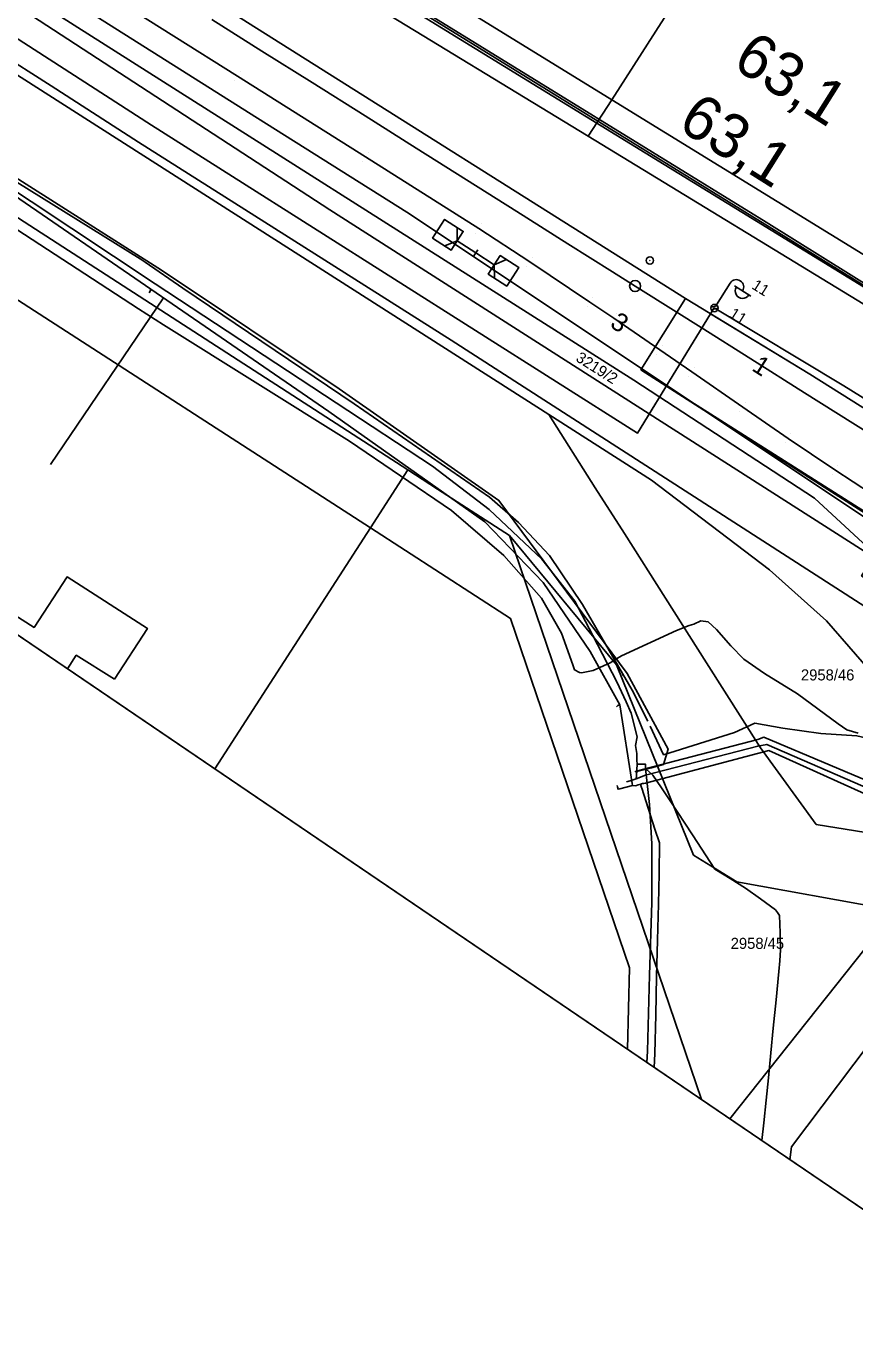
# Model space of a CAD drawing. Extents: x -621145 to -620110, y -1122807 to -1121971.
# Drawn here: x -620628.4 to -620515.9, y -1122662.4 to -1122484.3 of the extents above; entities that cross this region are included whole.
import ezdxf

# ---------------------------------------------------------------- set-up
doc = ezdxf.new("R2010")
doc.units = 0
for name, color, linetype in [('060601_EOV', 7, 'Continuous'), ('060604_ROZVODY_SEE', 7, 'Continuous'), ('CETIN', 7, 'Continuous'), ('GasNet', 7, 'Continuous'), ('itself', 7, 'Continuous'), ('PS 06-14-01_trasa_sdělovací_nové', 7, 'Continuous'), ('RÁMY', 7, 'Continuous'), ('SEE', 7, 'Continuous'), ('SSZT', 7, 'Continuous'), ('SSZT-DK', 7, 'Continuous'), ('UZEMNĚNÍ', 7, 'Continuous'), ('VAS stoka', 7, 'Continuous'), ('VAS vodovod', 7, 'Continuous'), ('Vrstva 1', 7, 'Continuous'), ('Vrstva 25', 7, 'Continuous'), ('Vrstva 53', 7, 'Continuous'), ('Vrstva 55', 7, 'Continuous'), ('Vrstva 56', 7, 'Continuous'), ('Vrstva 57', 7, 'Continuous'), ('Vrstva 62', 7, 'Continuous'), ('Vrstva 7', 7, 'Continuous'), ('ČD-T', 7, 'Continuous')]:
    doc.layers.add(name, color=color, linetype=linetype)

msp = doc.modelspace()

# ---------------------------------------------------------------- linework, layer by layer
at = {"layer": '060601_EOV'}
msp.add_lwpolyline([(-620343.18, -1122658.46), (-620368.5, -1122642.9), (-620411.56, -1122614.92), (-620424.16, -1122607.09), (-620443.53, -1122595), (-620456.11, -1122587.12), (-620447.82, -1122572.96), (-620450.95, -1122571.45), (-620470.59, -1122561.48), (-620499.61, -1122545.57), (-620522.04, -1122531.47), (-620538.89, -1122521.21), (-620599.21, -1122483.22), (-620683.52, -1122429.44)], dxfattribs=at)
at = {"layer": '060604_ROZVODY_SEE'}
msp.add_line((-620535, -1122522.48), (-620535.49, -1122523.28), dxfattribs=at)
msp.add_lwpolyline([(-620443.53, -1122595), (-620456.11, -1122587.12), (-620447.82, -1122572.96), (-620450.95, -1122571.45), (-620470.59, -1122561.48), (-620499.61, -1122545.57), (-620522.04, -1122531.47), (-620538.89, -1122521.21), (-620599.21, -1122483.22), (-620683.52, -1122429.44), (-620756.33, -1122383.52), (-620765.8, -1122398.39)], dxfattribs=at)
at = {"layer": 'CETIN'}
for points in [[(-620926.41, -1122268.7), (-620748.44, -1122376.27), (-620484.52, -1122538.15)], [(-620646.43, -1122495.05), (-620612.92, -1122515.84), (-620612.23, -1122516.26), (-620607.1, -1122519.79), (-620583.87, -1122535.51), (-620565.48, -1122548.17), (-620561.56, -1122551.58), (-620557.36, -1122556.05), (-620552.9, -1122562.72), (-620546.13, -1122574.35), (-620544.03, -1122578.53)], [(-620607.1, -1122519.79), (-620612.23, -1122516.26)], [(-620547.37, -1122572.22), (-620547.52, -1122572.29)], [(-620543.69, -1122579.2), (-620541.87, -1122583.1), (-620532.27, -1122580.05), (-620529.5, -1122578.82), (-620525.69, -1122579.49), (-620520.52, -1122580.2), (-620515.66, -1122580.54), (-620511.76, -1122581.44), (-620509.68, -1122582.26), (-620506.2, -1122582.41), (-620494.32, -1122581.82), (-620491.48, -1122581.44), (-620483.44, -1122578.57)], [(-620532.27, -1122580.05), (-620541.87, -1122583.1)]]:
    msp.add_lwpolyline(points, dxfattribs=at)
at = {"layer": 'GasNet'}
for points in [[(-620639.06, -1122500.54), (-620610.88, -1122519.2), (-620586.31, -1122535.34), (-620573.22, -1122543.96), (-620565.55, -1122549.81), (-620558.39, -1122556.56), (-620553.9, -1122562.25), (-620551.49, -1122566.93), (-620548.21, -1122573.19), (-620546.94, -1122575.89), (-620546.29, -1122577.44), (-620545.44, -1122580.66), (-620545.67, -1122581.84), (-620545.49, -1122582.92), (-620545.5, -1122583.84), (-620545.45, -1122584.35), (-620545.55, -1122585.95), (-620545.62, -1122586.36)], [(-620545.62, -1122586.36), (-620544.33, -1122585.86), (-620529.1, -1122581.91), (-620527.88, -1122581.68), (-620501.79, -1122593.01), (-620500.52, -1122592.53), (-620484.13, -1122585.56), (-620478.57, -1122583.14), (-620474.2, -1122586.82), (-620449.91, -1122606.86), (-620450.02, -1122607.5), (-620458.5, -1122620.02), (-620458.8, -1122620.62), (-620432.06, -1122640.49), (-620425.64, -1122643.91), (-620417.98, -1122647.99), (-620389.11, -1122672.47), (-620361.34, -1122696.38), (-620351.16, -1122708.72), (-620351, -1122709.02), (-620350.83, -1122709.39), (-620350.53, -1122710.79), (-620349.5, -1122710.44), (-620336.68, -1122702.48)], [(-620545.45, -1122584.35), (-620544.34, -1122584.36), (-620544.31, -1122584.94), (-620543.79, -1122589.85), (-620543.45, -1122595.16)], [(-620545.62, -1122586.36), (-620546.42, -1122586.61), (-620546.89, -1122586.78)], [(-620543.45, -1122595.16), (-620543.47, -1122603.15), (-620543.79, -1122613), (-620544.07, -1122623.3), (-620544.13, -1122624.83)]]:
    msp.add_lwpolyline(points, dxfattribs=at)
at = {"layer": 'itself'}
msp.add_lwpolyline([(-620515.49, -1122580.17), (-620517.02, -1122579.72), (-620518.2, -1122578.89), (-620523.69, -1122574.82), (-620528.2, -1122572.08), (-620530.97, -1122570.13), (-620532.77, -1122568.3), (-620534.7, -1122566.11), (-620535.82, -1122565.08), (-620536.83, -1122564.91), (-620537.77, -1122565.36), (-620538.42, -1122565.55), (-620540.13, -1122566.23), (-620547.57, -1122569.68), (-620548.37, -1122570.13), (-620549.14, -1122570.64), (-620551.44, -1122571.66), (-620553.02, -1122571.98), (-620553.03, -1122571.98), (-620553.3, -1122571.94), (-620553.95, -1122571.56), (-620554.18, -1122570.9), (-620555.72, -1122566.58), (-620558.44, -1122561.86), (-620563.55, -1122556.05), (-620570.67, -1122549.95), (-620584.48, -1122540.56), (-620609.76, -1122524.78), (-620613.13, -1122522.62), (-620616.25, -1122520.59), (-620644.13, -1122502.42)], dxfattribs=at)
at = {"layer": 'PS 06-14-01_trasa_sdělovací_nové'}
for points in [[(-620538.89, -1122521.21), (-620538.89, -1122521.21), (-620599.21, -1122483.22), (-620683.52, -1122429.44), (-620756.33, -1122383.52), (-620761.98, -1122392.4), (-620753.37, -1122398.54), (-620735.26, -1122410.11), (-620735.26, -1122410.11)], [(-620248.32, -1122722.77), (-620259.89, -1122713.57), (-620277.71, -1122700.89), (-620282.35, -1122705.3), (-620297.82, -1122689.49), (-620310.82, -1122680.06), (-620322.23, -1122672.32), (-620343.18, -1122658.46), (-620368.5, -1122642.9), (-620411.56, -1122614.92), (-620456.11, -1122587.12), (-620544.95, -1122530.86), (-620538.89, -1122521.21), (-620538.89, -1122521.21), (-620538.89, -1122521.21)]]:
    msp.add_lwpolyline(points, dxfattribs=at)
at = {"layer": 'RÁMY'}
for points in [[(-621061.56, -1122093.92), (-620192.94, -1122683.83), (-620276.37, -1122806.68), (-621144.99, -1122216.77)], [(-620887.83, -1122211.9), (-620192.94, -1122683.83), (-620276.37, -1122806.68), (-620971.26, -1122334.75)]]:
    msp.add_lwpolyline(points, close=True, dxfattribs=at)
at = {"layer": 'SEE'}
msp.add_lwpolyline([(-620244.52, -1122694.3), (-620246.55, -1122692.66), (-620267.47, -1122718.6), (-620268.22, -1122719.53), (-620284.41, -1122704.62), (-620304.33, -1122686.26), (-620309.55, -1122681.45), (-620327.71, -1122669.48), (-620362.83, -1122646.34), (-620390.25, -1122629.02), (-620411.93, -1122614.96), (-620423.13, -1122608.01), (-620468.34, -1122579.91), (-620468.34, -1122579.91), (-620460.94, -1122568.1), (-620517.42, -1122533.03), (-620535, -1122522.48), (-620545.41, -1122539.45), (-620611.37, -1122497.7), (-620665.57, -1122462.75)], dxfattribs=at)
at = {"layer": 'SSZT'}
msp.add_lwpolyline([(-620879.24, -1122313.32), (-620842.99, -1122336.61), (-620835.05, -1122343.25), (-620812.66, -1122358.95), (-620764.9, -1122389.75), (-620688.59, -1122438.97), (-620596.98, -1122496.73), (-620576.74, -1122509.48), (-620506.75, -1122556.12), (-620447.29, -1122593.62), (-620363.27, -1122647.56), (-620313.97, -1122679.22), (-620306.51, -1122669.29), (-620273.14, -1122696.27), (-620258.42, -1122709.14), (-620248.07, -1122696.09)], dxfattribs=at)
at = {"layer": 'SSZT-DK'}
msp.add_lwpolyline([(-620927.29, -1122269.99), (-620900.27, -1122286.47), (-620889.15, -1122293.45), (-620783.74, -1122358.82), (-620712.75, -1122398.18), (-620653.12, -1122435.23), (-620617.36, -1122456.74), (-620574.42, -1122482.6), (-620528.16, -1122511.11), (-620496.31, -1122530.83), (-620515.02, -1122558.81), (-620500.38, -1122568.61), (-620465.39, -1122591.45), (-620452.16, -1122605.02), (-620438.23, -1122615.5), (-620392.31, -1122655.21), (-620359.04, -1122685.8), (-620308.77, -1122717.8), (-620291.41, -1122732.21), (-620277.2, -1122744.11), (-620257.61, -1122720.05), (-620250.25, -1122710.72), (-620233.29, -1122724.26), (-620225.35, -1122731.56)], dxfattribs=at)
at = {"layer": 'UZEMNĚNÍ'}
msp.add_lwpolyline([(-620535, -1122522.48), (-620535.49, -1122523.28), (-620522.04, -1122531.47), (-620499.61, -1122545.57), (-620487.51, -1122552.2), (-620470.59, -1122561.48), (-620459.3, -1122567.21), (-620458.67, -1122565.97)], dxfattribs=at)
at = {"layer": 'VAS stoka'}
for points in [[(-620781.72, -1122408.87), (-620776.69, -1122412.14), (-620774.2, -1122412.02), (-620772.21, -1122412.95), (-620766.77, -1122415.95), (-620758.11, -1122421.89), (-620737.16, -1122435.39), (-620726.71, -1122442.22), (-620705.9, -1122455.54), (-620681.71, -1122471.08), (-620665.23, -1122481.83), (-620655.61, -1122488.12), (-620638.12, -1122499.53), (-620609.99, -1122517.38), (-620585.88, -1122533.44), (-620564.23, -1122548.6), (-620546.83, -1122572.05), (-620541.25, -1122582.33), (-620541.87, -1122584.42), (-620543.53, -1122584.85), (-620544.25, -1122585.03)], [(-620544.25, -1122585.03), (-620545.68, -1122585.41), (-620545.7, -1122585.34), (-620544.74, -1122585.09), (-620529.09, -1122581.01), (-620528.27, -1122580.72), (-620501.26, -1122592.08), (-620484.32, -1122584.76), (-620478.68, -1122582.19), (-620475.52, -1122584.33), (-620473.62, -1122582.33), (-620454.46, -1122552.49), (-620449.28, -1122555.81), (-620438.79, -1122557.25), (-620438.13, -1122557.28)], [(-620528.56, -1122635.4), (-620528.28, -1122633.03), (-620527.95, -1122629.96), (-620527.63, -1122626.89), (-620527.31, -1122623.54), (-620526.99, -1122620.19), (-620526.62, -1122616.34), (-620526.25, -1122612.49), (-620526.12, -1122611.03), (-620525.99, -1122609.57), (-620526.07, -1122607.23), (-620526.16, -1122604.89), (-620526.43, -1122604.5), (-620526.7, -1122604.12), (-620528.73, -1122602.65), (-620530.75, -1122601.19), (-620532.84, -1122599.89), (-620534.92, -1122598.59), (-620537.95, -1122593.97), (-620540.97, -1122589.34), (-620542.16, -1122587.59), (-620543.34, -1122585.84), (-620543.8, -1122585.43), (-620544.25, -1122585.03)]]:
    msp.add_lwpolyline(points, dxfattribs=at)
at = {"layer": 'VAS vodovod'}
msp.add_line((-620609.72, -1122521.13), (-620625.07, -1122543.73), dxfattribs=at)
for points in [[(-620783.05, -1122410.36), (-620779.49, -1122412.44), (-620776.82, -1122413.57), (-620766.15, -1122419), (-620759.23, -1122423.16), (-620738.05, -1122436.88), (-620666.7, -1122483.31), (-620630.69, -1122506.76), (-620611.44, -1122519.95), (-620587.32, -1122536.52), (-620566.14, -1122551.51), (-620558.22, -1122559.71), (-620551.85, -1122569.08), (-620547.83, -1122576.32), (-620546.15, -1122586.98), (-620546.1, -1122587.26)], [(-620611.68, -1122520.43), (-620611.56, -1122520.19), (-620611.44, -1122519.95)], [(-620548.28, -1122576.61), (-620548.08, -1122576.43), (-620547.83, -1122576.32)], [(-620544.97, -1122587.1), (-620544.86, -1122587.05), (-620544.76, -1122587), (-620544.54, -1122586.97), (-620544.31, -1122586.94), (-620527.61, -1122582.53), (-620502.02, -1122594.03), (-620500.78, -1122593.46), (-620500.1, -1122593.23), (-620483.67, -1122586.38), (-620481.33, -1122585.41), (-620479.58, -1122584.86), (-620478.41, -1122584.64), (-620477.75, -1122585.1), (-620476.87, -1122585.61)], [(-620546.1, -1122587.26), (-620547.82, -1122587.71), (-620548.06, -1122587.76), (-620548.14, -1122587.45), (-620548.19, -1122587.25)], [(-620546.1, -1122587.26), (-620545.74, -1122587.29), (-620545.54, -1122587.24), (-620545.34, -1122587.19), (-620545.15, -1122587.14), (-620544.97, -1122587.1)], [(-620544.97, -1122587.1), (-620544.95, -1122587.25), (-620544.93, -1122587.4), (-620544.87, -1122587.52), (-620544.81, -1122587.64), (-620544.23, -1122589.49), (-620543.66, -1122591.34), (-620543.05, -1122593.19), (-620542.44, -1122595.03), (-620542.49, -1122599.19), (-620542.55, -1122603.34), (-620542.69, -1122608.25), (-620542.83, -1122613.15), (-620542.95, -1122618.38), (-620543.07, -1122623.6), (-620543.15, -1122625.5)]]:
    msp.add_lwpolyline(points, dxfattribs=at)
at = {"layer": 'Vrstva 1'}
msp.add_line((-620544.95, -1122530.86), (-620538.89, -1122521.21), dxfattribs=at)
for points in [[(-620538.89, -1122521.21), (-620599.21, -1122483.22), (-620683.52, -1122429.44), (-620747.38, -1122389.13), (-620756.33, -1122383.52)], [(-620616.99, -1122480.17), (-620599.71, -1122491.04), (-620582.33, -1122501.97), (-620566.97, -1122511.73), (-620560.03, -1122516.24), (-620551.87, -1122521.69), (-620548.62, -1122523.89), (-620542.4, -1122528.15), (-620538.06, -1122531.16), (-620531.12, -1122535.95), (-620524.97, -1122540.18), (-620518.62, -1122544.43), (-620513.65, -1122547.7)], [(-620603.19, -1122483.36), (-620596.39, -1122487.64), (-620589.57, -1122491.93), (-620582.39, -1122496.45), (-620575.44, -1122500.82), (-620568.6, -1122505.12), (-620561.8, -1122509.42), (-620554.88, -1122513.77), (-620548.82, -1122517.58), (-620545.74, -1122519.52), (-620540.16, -1122523.03), (-620536.76, -1122525.16), (-620530.04, -1122529.4), (-620522.74, -1122534), (-620516.18, -1122538.13), (-620510.88, -1122541.46)], [(-620603.19, -1122483.36), (-620596.39, -1122487.64), (-620589.57, -1122491.93), (-620582.39, -1122496.45), (-620575.44, -1122500.82), (-620568.6, -1122505.12), (-620561.8, -1122509.42), (-620554.88, -1122513.77), (-620548.82, -1122517.58), (-620545.74, -1122519.52), (-620540.16, -1122523.03), (-620536.76, -1122525.16), (-620530.04, -1122529.4), (-620522.74, -1122534), (-620516.18, -1122538.13), (-620510.88, -1122541.46)], [(-620456.11, -1122587.12), (-620500.01, -1122559.59), (-620522.22, -1122545.45), (-620544.95, -1122530.86)]]:
    msp.add_lwpolyline(points, dxfattribs=at)
at = {"layer": 'Vrstva 25'}
for p, q in [((-620534.71, -1122522.08), (-620532.84, -1122519.12)), ((-620534.71, -1122522.08), (-620532.84, -1122519.12)), ((-620532.25, -1122519.49), (-620530.05, -1122520.88)), ((-620532.25, -1122519.49), (-620530.05, -1122520.88)), ((-620535.46, -1122522.37), (-620534.6, -1122522.18)), ((-620535.46, -1122522.37), (-620534.6, -1122522.18)), ((-620535.41, -1122522.74), (-620534.48, -1122522.53)), ((-620535.41, -1122522.74), (-620534.48, -1122522.53))]:
    msp.add_line(p, q, dxfattribs=at)
msp.add_circle((-620534.98, -1122522.5), 0.5, dxfattribs=at)
msp.add_circle((-620534.98, -1122522.5), 0.5, dxfattribs=at)
for centre, start, end in [((-620532, -1122519.65), 327.7645, 147.7645), ((-620532, -1122519.65), 327.7645, 147.7645), ((-620531.16, -1122520.19), 147.0619, 328.467), ((-620531.16, -1122520.19), 147.0619, 328.467)]:
    msp.add_arc(centre, 1, start, end, dxfattribs=at)
at = {"layer": 'Vrstva 53'}
for p, q in [((-620545.92, -1122532.26), (-620679.51, -1122447.56)), ((-620638.48, -1122446.57), (-620552.09, -1122499.2)), ((-620552.09, -1122499.2), (-620445.8, -1122563.95)), ((-620521.41, -1122548.27), (-620545.92, -1122532.26)), ((-620511.29, -1122557.64), (-620521.41, -1122548.27))]:
    msp.add_line(p, q, dxfattribs=at)
at = {"layer": 'Vrstva 55'}
for p, q in [((-620688.16, -1122408.5), (-620548.9, -1122494.24)), ((-620545.92, -1122532.26), (-620679.51, -1122447.56)), ((-620638.48, -1122446.57), (-620552.09, -1122499.2)), ((-620557.45, -1122536.96), (-620684.91, -1122455.63)), ((-620548.9, -1122494.24), (-620525.58, -1122457.92)), ((-620587.17, -1122509.18), (-620645.72, -1122471.03)), ((-620576.58, -1122544.45), (-620660.74, -1122490.09)), ((-620552.09, -1122499.2), (-620548.9, -1122494.24)), ((-620548.9, -1122494.24), (-620475.79, -1122539.24)), ((-620552.09, -1122499.2), (-620445.8, -1122563.95)), ((-620657.43, -1122503.38), (-620581.67, -1122552.32)), ((-620511.29, -1122557.64), (-620587.17, -1122509.18)), ((-620521.41, -1122548.27), (-620545.92, -1122532.26)), ((-620557.45, -1122536.96), (-620551.15, -1122546.87)), ((-620543.5, -1122545.86), (-620557.45, -1122536.96)), ((-620581.67, -1122552.32), (-620576.58, -1122544.45)), ((-620543.5, -1122545.86), (-620527.5, -1122558.02)), ((-620551.15, -1122546.87), (-620547.19, -1122553.1)), ((-620511.29, -1122557.64), (-620521.41, -1122548.27)), ((-620581.67, -1122552.32), (-620602.78, -1122585)), ((-620548.28, -1122570.88), (-620562.8, -1122553.35)), ((-620562.8, -1122553.35), (-620536.71, -1122629.87)), ((-620547.19, -1122553.1), (-620536.04, -1122570.64)), ((-620519.77, -1122564.93), (-620527.5, -1122558.02)), ((-620511.02, -1122574.99), (-620519.77, -1122564.93)), ((-620537.83, -1122596.73), (-620548.28, -1122570.88)), ((-620536.04, -1122570.64), (-620528.72, -1122582.15)), ((-620528.72, -1122582.15), (-620521.17, -1122592.53)), ((-620521.17, -1122592.53), (-620510.22, -1122594.3)), ((-620531.96, -1122600.32), (-620537.83, -1122596.73)), ((-620510.44, -1122604.21), (-620531.96, -1122600.32)), ((-620532.9, -1122632.46), (-620510.44, -1122604.21)), ((-620503.19, -1122607.95), (-620524.52, -1122636.25)), ((-620524.73, -1122638.01), (-620524.52, -1122636.25))]:
    msp.add_line(p, q, dxfattribs=at)
for points in [[(-620562.8, -1122553.35), (-620572.54, -1122547.06), (-620576.58, -1122544.45)], [(-620659.82, -1122546.26), (-620659.27, -1122545.41), (-620652.1, -1122549.99), (-620627.31, -1122565.82), (-620622.82, -1122558.97), (-620611.91, -1122565.95), (-620616.39, -1122572.84)], [(-620581.67, -1122552.32), (-620562.67, -1122564.59), (-620546.5, -1122612), (-620546.78, -1122623.03)], [(-620616.39, -1122572.84), (-620621.58, -1122569.6), (-620622.76, -1122571.43)]]:
    msp.add_lwpolyline(points, dxfattribs=at)
at = {"layer": 'Vrstva 56'}
for p, q in [((-620648.08, -1122477.56), (-620625, -1122492.37)), ((-620625, -1122492.37), (-620613.12, -1122500)), ((-620570.69, -1122526.84), (-620613.12, -1122500)), ((-620504.94, -1122569.2), (-620570.69, -1122526.84))]:
    msp.add_line(p, q, dxfattribs=at)
at = {"layer": 'Vrstva 62'}
for p, q in [((-620599.33, -1122490.43), (-620599.33, -1122490.43)), ((-620600.08, -1122491.66), (-620600.08, -1122491.66)), ((-620581.93, -1122501.35), (-620581.93, -1122501.35)), ((-620582.73, -1122502.59), (-620582.73, -1122502.59)), ((-620567.35, -1122512.35), (-620567.35, -1122512.35)), ((-620566.6, -1122511.1), (-620566.6, -1122511.1)), ((-620559.63, -1122515.64), (-620559.63, -1122515.64)), ((-620560.43, -1122516.84), (-620560.43, -1122516.84)), ((-620551.48, -1122521.07), (-620551.48, -1122521.07)), ((-620552.26, -1122522.3), (-620552.26, -1122522.3)), ((-620549.02, -1122524.5), (-620549.02, -1122524.5)), ((-620548.22, -1122523.28), (-620548.22, -1122523.28)), ((-620542.01, -1122527.53), (-620542.01, -1122527.53)), ((-620542.78, -1122528.77), (-620542.78, -1122528.77)), ((-620538.47, -1122531.76), (-620538.47, -1122531.76)), ((-620537.66, -1122530.55), (-620537.66, -1122530.55)), ((-620530.74, -1122535.33), (-620530.74, -1122535.33)), ((-620531.51, -1122536.57), (-620531.51, -1122536.57)), ((-620525.34, -1122540.79), (-620525.34, -1122540.79)), ((-620524.59, -1122539.57), (-620524.59, -1122539.57)), ((-620518.23, -1122543.81), (-620518.23, -1122543.81)), ((-620519, -1122545.04), (-620519, -1122545.04))]:
    msp.add_line(p, q, dxfattribs=at)
at = {"layer": 'Vrstva 7'}
for p, q in [((-620569.89, -1122513.37), (-620567.37, -1122515.01)), ((-620567.64, -1122515.43), (-620567.1, -1122514.59)), ((-620567.1, -1122514.59), (-620567.64, -1122515.43)), ((-620564.86, -1122516.64), (-620567.37, -1122515.01)), ((-620543.78, -1122516.02), (-620543.69, -1122516.08)), ((-620543.78, -1122516.02), (-620543.69, -1122516.08))]:
    msp.add_line(p, q, dxfattribs=at)
for points in [[(-620569.89, -1122513.37), (-620569.07, -1122512.11), (-620571.59, -1122510.48), (-620573.22, -1122513), (-620570.7, -1122514.63), (-620569.89, -1122513.37)], [(-620571.55, -1122514.08), (-620569.89, -1122513.37), (-620569.91, -1122511.57)], [(-620564.86, -1122516.64), (-620565.67, -1122517.9), (-620563.16, -1122519.53), (-620561.52, -1122517.02), (-620564.04, -1122515.38), (-620564.86, -1122516.64)], [(-620563.2, -1122515.93), (-620564.86, -1122516.64), (-620564.83, -1122518.44)]]:
    msp.add_lwpolyline(points, dxfattribs=at)
for centre, radius in [((-620543.73, -1122516.05), 0.5), ((-620543.73, -1122516.05), 0.5), ((-620545.74, -1122519.52), 0.75), ((-620545.74, -1122519.52), 0.75)]:
    msp.add_circle(centre, radius, dxfattribs=at)
at = {"layer": 'ČD-T'}
msp.add_lwpolyline([(-620927.12, -1122269.75), (-620900.08, -1122286.23), (-620888.96, -1122293.22), (-620783.56, -1122358.58), (-620712.56, -1122397.94), (-620652.93, -1122435), (-620617.18, -1122456.5), (-620574.24, -1122482.37), (-620527.97, -1122510.87), (-620481.08, -1122540.08), (-620497, -1122565.38), (-620499.27, -1122568.98), (-620465.21, -1122591.22), (-620451.97, -1122604.79), (-620438.05, -1122615.26), (-620392.12, -1122654.98), (-620358.85, -1122685.56), (-620308.58, -1122717.56), (-620291.22, -1122731.97), (-620279.98, -1122741.46), (-620260.48, -1122717.47), (-620252.94, -1122708.19), (-620233.1, -1122724.03), (-620225.18, -1122731.31)], dxfattribs=at)

# ---------------------------------------------------------------- texts
at = {"layer": 'Vrstva 1'}
for s, rotation, p in [('3', 325.5811, (-620549.29, -1122524.94)), ('1', 327.8088, (-620530.05, -1122530.88))]:
    msp.add_text(s, height=2.5, rotation=rotation, dxfattribs=at).set_placement(p)
at = {"layer": 'Vrstva 25'}
for p in [(-620530.03, -1122519.78), (-620533.09, -1122523.63)]:
    msp.add_text('11', height=1.5, rotation=327.7645, dxfattribs=at).set_placement(p)
at = {"layer": 'Vrstva 57'}
msp.add_text('3219/2', height=1.5, rotation=327.6, dxfattribs=at).set_placement((-620553.91, -1122529.6))
for s, p in [('2958/46', (-620523.24, -1122573.01)), ('2958/45', (-620532.77, -1122609.42))]:
    msp.add_text(s, height=1.5, dxfattribs=at).set_placement(p)
at = {"layer": 'Vrstva 7'}
for p in [(-620532.74, -1122489.74), (-620540.16, -1122498.07)]:
    msp.add_text('63,1', height=6, rotation=327.8195, dxfattribs=at).set_placement(p)

doc.saveas('drawing.dxf')
